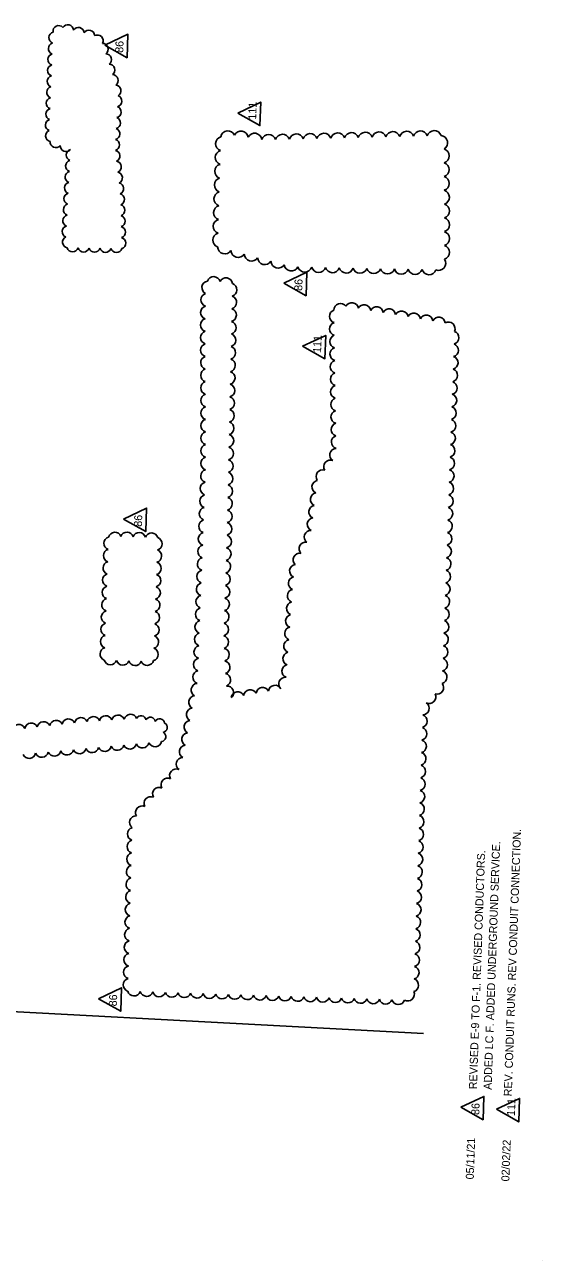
# Model space of a CAD drawing. Extents: x 928669 to 929521, y 636891 to 638153.
# Drawn here: x 929187 to 929497, y 636891 to 637632 of the extents above; entities that cross this region are included whole.
import ezdxf

# ---------------------------------------------------------------- set-up
doc = ezdxf.new("R2010")
doc.units = 0
for name, color, linetype in [('AdhocPoint_dp', 7, 'Continuous'), ('Cloud_dp', 7, 'Continuous'), ('MatchLines_dp', 7, 'Continuous')]:
    doc.layers.add(name, color=color, linetype=linetype)

msp = doc.modelspace()

# ---------------------------------------------------------------- linework, layer by layer
at = {"layer": 'AdhocPoint_dp'}
msp.add_line((929497.23, 636890.88), (929497.23, 636890.88), dxfattribs=at)
at = {"layer": 'Cloud_dp'}
for points in [[(929235.2, 637619.48), (929248.51, 637611.96), (929249, 637626.04)], [(929314.8, 637578.72), (929328.11, 637571.21), (929328.6, 637585.29)], [(929342.46, 637476.74), (929355.77, 637469.23), (929356.26, 637483.31)], [(929353.7, 637438.9), (929367.01, 637431.39), (929367.5, 637445.47)], [(929246.44, 637335.3), (929259.74, 637327.79), (929260.24, 637341.87)], [(929231.39, 637047.73), (929244.7, 637040.22), (929245.19, 637054.29)], [(929448.5, 636982.61), (929461.8, 636975.1), (929462.3, 636989.17)], [(929469.81, 636981.4), (929483.12, 636973.89), (929483.61, 636987.96)]]:
    msp.add_lwpolyline(points, close=True, dxfattribs=at)
for centre, radius, start, end in [((929213.02, 637628.29), 3.44, 2.92703, 147.92703), ((929205.1, 637623.96), 3.44, 105.27092, 250.27092), ((929207.6, 637627.76), 3.44, 43.1629, 188.1629), ((929219.37, 637626.64), 3.44, 2.92703, 147.92703), ((929225.72, 637624.99), 3.44, 2.92703, 147.92703), ((929230.75, 637622.12), 3.44, 332.6769, 117.6769), ((929204.85, 637617.4), 3.44, 105.27092, 250.27092), ((929233.82, 637617.1), 3.44, 305.17358, 90.17358), ((929204.59, 637610.85), 3.44, 105.27092, 250.27092), ((929235.81, 637610.85), 3.44, 305.17358, 90.17358), ((929204.34, 637604.29), 3.44, 105.27092, 250.27092), ((929237.8, 637604.6), 3.44, 305.17358, 90.17358), ((929239.79, 637598.35), 3.44, 305.17358, 90.17358), ((929203.83, 637591.18), 3.44, 105.27092, 250.27092), ((929204.08, 637597.74), 3.44, 105.27092, 250.27092), ((929241.46, 637592.11), 3.44, 299.75137, 84.75137), ((929203.57, 637584.63), 3.44, 105.27092, 250.27092), ((929241.94, 637585.92), 3.44, 284.10958, 69.10958), ((929203.32, 637578.07), 3.44, 105.27092, 250.27092), ((929241.55, 637579.37), 3.44, 284.10958, 69.10958), ((929203.06, 637571.52), 3.44, 105.27092, 250.27092), ((929241.16, 637572.82), 3.44, 284.10958, 69.10958), ((929203.18, 637565.09), 3.44, 111.86507, 256.86507), ((929240.78, 637566.27), 3.44, 284.10958, 69.10958), ((929308.97, 637563.74), 4.33, 24.68742, 169.68742), ((929316.78, 637563.62), 4.33, 8.49645, 153.49645), ((929324.94, 637562.33), 4.33, 8.49645, 153.49645), ((929333.34, 637561.62), 4.34, 16.93077, 161.93077), ((929341.65, 637561.68), 4.33, 18.88115, 163.88115), ((929349.91, 637561.88), 4.33, 18.88115, 163.88115), ((929358.17, 637562.08), 4.33, 18.88115, 163.88115), ((929366.43, 637562.28), 4.33, 18.88115, 163.88115), ((929374.69, 637562.48), 4.33, 18.88115, 163.88115), ((929382.95, 637562.68), 4.33, 18.88115, 163.88115), ((929391.21, 637562.88), 4.33, 18.88115, 163.88115), ((929399.47, 637563.08), 4.33, 18.88115, 163.88115), ((929407.73, 637563.28), 4.33, 18.88115, 163.88115), ((929415.99, 637563.47), 4.33, 18.88115, 163.88115), ((929424.25, 637563.67), 4.33, 18.88115, 163.88115), ((929432.51, 637563.87), 4.33, 18.88115, 163.88115), ((929436.25, 637560.96), 4.33, 300.25152, 85.25152), ((929205.83, 637561.48), 3.44, 175.6731, 320.6731), ((929211.92, 637559.04), 3.44, 175.6731, 320.6731), ((929240.54, 637559.67), 3.44, 286.70334, 71.70334), ((929305.89, 637560.35), 4.33, 105.83297, 250.83297), ((929437.15, 637553.08), 4.33, 287.75579, 72.75579), ((929215.19, 637546.97), 3.44, 104.44225, 249.44225), ((929215.49, 637553.55), 3.44, 105.4204, 250.4204), ((929240.86, 637553), 3.44, 293.9345, 78.9345), ((929241.6, 637546.48), 3.44, 293.9345, 78.9345), ((929305.65, 637552.09), 4.33, 105.83297, 250.83297), ((929214.85, 637540.42), 3.44, 104.44225, 249.44225), ((929242.33, 637539.96), 3.44, 293.9345, 78.9345), ((929305.41, 637543.83), 4.33, 105.83297, 250.83297), ((929437.19, 637544.82), 4.33, 287.75579, 72.75579), ((929214.5, 637533.87), 3.44, 104.44225, 249.44225), ((929243.07, 637533.45), 3.44, 293.9345, 78.9345), ((929305.17, 637535.57), 4.33, 105.83297, 250.83297), ((929437.22, 637536.55), 4.33, 287.75579, 72.75579), ((929214.15, 637527.32), 3.44, 104.44225, 249.44225), ((929243.57, 637526.98), 3.44, 289.97064, 74.97064), ((929304.93, 637527.31), 4.33, 105.83297, 250.83297), ((929437.26, 637528.29), 4.33, 287.75579, 72.75579), ((929213.8, 637520.77), 3.44, 104.44225, 249.44225), ((929243.8, 637520.44), 3.44, 289.01338, 74.01338), ((929304.69, 637519.06), 4.33, 105.83297, 250.83297), ((929437.3, 637520.03), 4.33, 287.75579, 72.75579), ((929213.45, 637514.22), 3.44, 104.44225, 249.44225), ((929243.97, 637513.89), 3.44, 289.01338, 74.01338), ((929304.45, 637510.8), 4.33, 105.83297, 250.83297), ((929437.34, 637511.77), 4.33, 287.75579, 72.75579), ((929213.1, 637507.67), 3.44, 104.44225, 249.44225), ((929244.15, 637507.33), 3.44, 289.01338, 74.01338), ((929304.21, 637502.54), 4.33, 105.83297, 250.83297), ((929437.37, 637503.5), 4.33, 287.75579, 72.75579), ((929213.29, 637501.31), 3.44, 114.12608, 259.12608), ((929215.94, 637498.93), 3.44, 196.77389, 341.77389), ((929244.32, 637500.77), 3.44, 289.01338, 74.01338), ((929307.11, 637498.64), 4.33, 182.52043, 327.52043), ((929437.41, 637495.24), 4.33, 287.75579, 72.75579), ((929222.5, 637498.85), 3.44, 196.77389, 341.77389), ((929229.06, 637498.76), 3.44, 196.77389, 341.77389), ((929235.61, 637498.68), 3.44, 196.77389, 341.77389), ((929242.17, 637498.6), 3.44, 196.77389, 341.77389), ((929315.09, 637496.5), 4.33, 182.52043, 327.52043), ((929323.08, 637494.36), 4.33, 182.52043, 327.52043), ((929331.06, 637492.23), 4.33, 182.52043, 327.52043), ((929435.09, 637488.76), 4.33, 247.90789, 32.90789), ((929339.04, 637490.09), 4.33, 182.52043, 327.52043), ((929346.98, 637488.41), 4.33, 188.59745, 333.59745), ((929355.01, 637487.7), 4.33, 196.29364, 341.29364), ((929363.27, 637487.53), 4.33, 196.29364, 341.29364), ((929371.54, 637487.36), 4.33, 196.29364, 341.29364), ((929379.8, 637487.18), 4.33, 196.29364, 341.29364), ((929388.06, 637487.01), 4.33, 196.29364, 341.29364), ((929396.32, 637486.83), 4.33, 196.29364, 341.29364), ((929404.58, 637486.66), 4.33, 196.29364, 341.29364), ((929412.84, 637486.49), 4.33, 196.29364, 341.29364), ((929421.1, 637486.31), 4.33, 196.29364, 341.29364), ((929429.36, 637486.14), 4.33, 196.29364, 341.29364), ((929297.31, 637474.09), 3.95, 99.12031, 244.12031), ((929300.43, 637476.72), 3.95, 16.27485, 161.27485), ((929307.72, 637475.98), 3.95, 7.11778, 152.11778), ((929310.37, 637472.73), 3.95, 286.27485, 71.27485), ((929296.69, 637466.74), 3.95, 106.27485, 251.27485), ((929310.21, 637465.19), 3.95, 286.27485, 71.27485), ((929296.56, 637459.2), 3.95, 106.77607, 251.77607), ((929310.05, 637457.65), 3.95, 286.27485, 71.27485), ((929376.38, 637460.63), 3.95, 35.3298, 180.3298), ((929383.13, 637461.12), 3.95, 8.00095, 153.00095), ((929390.57, 637459.88), 3.95, 8.00095, 153.00095), ((929398.01, 637458.63), 3.95, 8.00095, 153.00095), ((929405.45, 637457.39), 3.95, 8.00095, 153.00095), ((929296.52, 637451.68), 3.95, 107.61007, 252.61007), ((929309.89, 637450.1), 3.95, 286.27485, 71.27485), ((929373.68, 637456.86), 3.95, 108.39751, 253.39751), ((929412.89, 637456.14), 3.95, 8.00095, 153.00095), ((929420.33, 637454.9), 3.95, 8.00095, 153.00095), ((929427.77, 637453.65), 3.95, 8.00095, 153.00095), ((929435.21, 637452.41), 3.95, 8.00095, 153.00095), ((929441.08, 637449.52), 3.95, 334.60056, 119.60056), ((929296.54, 637444.13), 3.95, 107.61007, 252.61007), ((929309.73, 637442.56), 3.95, 286.27485, 71.27485), ((929373.8, 637449.31), 3.95, 108.39751, 253.39751), ((929443.34, 637444.1), 3.95, 285.49782, 70.49782), ((929296.55, 637436.59), 3.95, 107.61007, 252.61007), ((929309.57, 637435.02), 3.95, 286.27485, 71.27485), ((929373.92, 637441.77), 3.95, 108.39751, 253.39751), ((929443.07, 637436.56), 3.95, 285.49782, 70.49782), ((929296.57, 637429.05), 3.95, 107.61007, 252.61007), ((929309.41, 637427.48), 3.95, 286.27485, 71.27485), ((929374.03, 637434.23), 3.95, 108.39751, 253.39751), ((929442.81, 637429.02), 3.95, 285.49782, 70.49782), ((929296.58, 637421.5), 3.95, 107.61007, 252.61007), ((929374.15, 637426.69), 3.95, 108.39751, 253.39751), ((929442.54, 637421.48), 3.95, 285.49782, 70.49782), ((929296.59, 637413.96), 3.95, 107.61007, 252.61007), ((929309.24, 637419.94), 3.95, 286.27485, 71.27485), ((929374.27, 637419.14), 3.95, 108.39751, 253.39751), ((929442.28, 637413.94), 3.95, 285.49782, 70.49782), ((929296.61, 637406.42), 3.95, 107.61007, 252.61007), ((929309.08, 637412.4), 3.95, 286.27485, 71.27485), ((929374.39, 637411.6), 3.95, 108.39751, 253.39751), ((929442.02, 637406.4), 3.95, 285.49782, 70.49782), ((929296.62, 637398.87), 3.95, 107.61007, 252.61007), ((929308.92, 637404.85), 3.95, 286.27485, 71.27485), ((929374.51, 637404.06), 3.95, 108.39751, 253.39751), ((929441.75, 637398.86), 3.95, 285.49782, 70.49782), ((929296.64, 637391.33), 3.95, 107.61007, 252.61007), ((929308.76, 637397.31), 3.95, 286.27485, 71.27485), ((929374.62, 637396.52), 3.95, 108.39751, 253.39751), ((929441.49, 637391.32), 3.95, 285.49782, 70.49782), ((929296.65, 637383.79), 3.95, 107.61007, 252.61007), ((929308.6, 637389.77), 3.95, 286.27485, 71.27485), ((929374.74, 637388.97), 3.95, 108.39751, 253.39751), ((929441.23, 637383.79), 3.95, 285.49782, 70.49782), ((929296.67, 637376.24), 3.95, 107.61007, 252.61007), ((929308.44, 637382.23), 3.95, 286.27485, 71.27485), ((929374.86, 637381.43), 3.96, 108.39751, 253.39751), ((929440.96, 637376.25), 3.95, 285.49782, 70.49782), ((929296.68, 637368.7), 3.95, 107.61007, 252.61007), ((929308.28, 637374.69), 3.95, 286.27485, 71.27485), ((929373.89, 637373.69), 3.95, 92.3374, 237.3374), ((929440.7, 637368.71), 3.95, 285.49782, 70.49782), ((929296.57, 637361.12), 3.95, 105.69752, 250.69752), ((929308.11, 637367.15), 3.95, 286.27485, 71.27485), ((929365.68, 637360.81), 3.95, 71.34179, 216.34179), ((929370.27, 637366.7), 3.95, 67.83576, 212.83576), ((929440.44, 637361.17), 3.95, 285.49782, 70.49782), ((929296.31, 637353.57), 3.95, 105.31641, 250.31641), ((929307.95, 637359.6), 3.95, 286.27485, 71.27485), ((929363.21, 637354.57), 3.95, 100.45276, 245.45276), ((929440.17, 637353.63), 3.95, 285.49782, 70.49782), ((929296.02, 637346.04), 3.95, 105.31641, 250.31641), ((929307.79, 637352.06), 3.95, 286.27485, 71.27485), ((929362.29, 637347.09), 3.95, 100.45276, 245.45276), ((929439.91, 637346.09), 3.95, 285.49782, 70.49782), ((929295.73, 637338.5), 3.95, 105.31641, 250.31641), ((929307.63, 637344.52), 3.95, 286.27485, 71.27485), ((929361.36, 637339.6), 3.95, 100.45276, 245.45276), ((929439.65, 637338.55), 3.95, 285.49782, 70.49782), ((929307.47, 637336.98), 3.95, 286.27485, 71.27485), ((929360.43, 637332.11), 3.96, 100.45276, 245.45276), ((929248.47, 637323.64), 3.87, 15.49782, 160.49782), ((929295.44, 637330.96), 3.95, 105.31641, 250.31641), ((929307.31, 637329.44), 3.95, 286.27485, 71.27485), ((929358.61, 637324.57), 3.95, 87.3831, 232.3831), ((929439.38, 637331.01), 3.95, 285.49782, 70.49782), ((929238.51, 637320.76), 3.87, 105.49782, 250.49782), ((929241.22, 637323.55), 3.86, 21.00152, 166.00152), ((929255.84, 637323.39), 3.87, 15.49782, 160.49782), ((929263.21, 637323.13), 3.87, 15.49782, 160.49782), ((929265.64, 637320.52), 3.87, 285.49782, 70.49782), ((929295.16, 637323.42), 3.95, 105.31641, 250.31641), ((929307.11, 637321.91), 3.95, 285.67169, 70.67169), ((929355.49, 637317.54), 3.95, 79.64936, 224.64936), ((929439.12, 637323.48), 3.95, 285.49782, 70.49782), ((929238.25, 637313.39), 3.87, 105.49782, 250.49782), ((929265.39, 637313.15), 3.87, 285.49782, 70.49782), ((929294.87, 637315.88), 3.95, 105.31641, 250.31641), ((929306.86, 637314.37), 3.95, 285.59211, 70.59211), ((929351.96, 637310.88), 3.95, 79.64936, 224.64936), ((929438.85, 637315.94), 3.95, 285.49782, 70.49782), ((929237.99, 637306.02), 3.87, 105.49782, 250.49782), ((929265.13, 637305.78), 3.87, 285.49782, 70.49782), ((929294.58, 637308.35), 3.95, 105.31641, 250.31641), ((929306.61, 637306.83), 3.95, 285.59211, 70.59211), ((929349.84, 637304.2), 3.96, 100.03505, 245.03505), ((929438.59, 637308.4), 3.95, 285.49782, 70.49782), ((929237.74, 637298.65), 3.87, 105.49782, 250.49782), ((929264.87, 637298.41), 3.87, 285.49782, 70.49782), ((929294.29, 637300.81), 3.95, 105.31641, 250.31641), ((929306.36, 637299.29), 3.95, 285.59211, 70.59211), ((929349.08, 637296.77), 3.95, 103.32391, 248.32391), ((929438.33, 637300.86), 3.95, 285.49782, 70.49782), ((929237.48, 637291.29), 3.87, 105.49782, 250.49782), ((929264.61, 637291.04), 3.87, 285.49782, 70.49782), ((929294.01, 637293.27), 3.95, 105.31641, 250.31641), ((929306.11, 637291.75), 3.95, 285.59211, 70.59211), ((929348.53, 637289.24), 3.95, 103.32391, 248.32391), ((929438.06, 637293.32), 3.95, 285.49782, 70.49782), ((929237.22, 637283.92), 3.87, 105.49782, 250.49782), ((929264.36, 637283.68), 3.87, 285.49782, 70.49782), ((929293.72, 637285.73), 3.95, 105.31641, 250.31641), ((929305.86, 637284.21), 3.95, 285.59211, 70.59211), ((929347.98, 637281.72), 3.95, 103.32391, 248.32391), ((929437.8, 637285.78), 3.95, 285.49782, 70.49782), ((929236.96, 637276.55), 3.87, 105.49782, 250.49782), ((929264.1, 637276.31), 3.87, 285.49782, 70.49782), ((929293.43, 637278.19), 3.95, 105.31641, 250.31641), ((929305.61, 637276.68), 3.95, 285.59211, 70.59211), ((929347.43, 637274.2), 3.95, 103.32391, 248.32391), ((929437.54, 637278.24), 3.95, 285.49782, 70.49782), ((929236.71, 637269.18), 3.87, 105.49782, 250.49782), ((929263.84, 637268.94), 3.87, 285.49782, 70.49782), ((929293.15, 637270.66), 3.95, 105.31641, 250.31641), ((929305.36, 637269.14), 3.95, 285.59211, 70.59211), ((929346.89, 637266.67), 3.95, 103.32391, 248.32391), ((929437.27, 637270.7), 3.95, 285.49782, 70.49782), ((929236.45, 637261.81), 3.87, 105.49782, 250.49782), ((929263.58, 637261.57), 3.87, 285.49782, 70.49782), ((929292.86, 637263.12), 3.95, 105.31641, 250.31641), ((929305.39, 637261.51), 3.95, 289.9101, 74.9101), ((929346.34, 637259.15), 3.95, 103.32391, 248.32391), ((929437.01, 637263.17), 3.95, 285.49782, 70.49782), ((929236.19, 637254.44), 3.87, 105.49782, 250.49782), ((929263.33, 637254.2), 3.87, 285.49782, 70.49782), ((929292.57, 637255.58), 3.95, 105.31641, 250.31641), ((929305.76, 637253.96), 3.95, 290.73051, 75.73051), ((929345.79, 637251.63), 3.95, 103.32391, 248.32391), ((929436.75, 637255.63), 3.95, 285.49782, 70.49782), ((929238.62, 637251.83), 3.87, 195.49782, 340.49782), ((929245.99, 637251.58), 3.87, 195.49782, 340.49782), ((929253.36, 637251.32), 3.87, 195.49782, 340.49782), ((929260.61, 637251.41), 3.86, 201.00152, 346.00152), ((929292.28, 637248.04), 3.95, 105.31641, 250.31641), ((929306.19, 637246.43), 3.95, 290.73051, 75.73051), ((929345.24, 637244.1), 3.96, 103.32391, 248.32391), ((929436.48, 637248.09), 3.95, 285.49782, 70.49782), ((929291.88, 637240.48), 3.95, 103.59365, 248.59365), ((929306.61, 637238.89), 3.95, 290.73051, 75.73051), ((929343.32, 637236.5), 3.95, 83.29548, 228.29548), ((929436.22, 637240.55), 3.95, 285.49782, 70.49782), ((929290.89, 637232.87), 3.95, 96.63256, 241.63256), ((929308.4, 637231.26), 3.96, 310.65902, 95.65902), ((929314.9, 637227.75), 3.96, 27.60024, 172.60024), ((929322.33, 637229.07), 3.95, 27.60024, 172.60024), ((929329.75, 637230.39), 3.95, 27.60024, 172.60024), ((929337.18, 637231.72), 3.95, 27.60024, 172.60024), ((929434.18, 637234.28), 3.95, 253.37458, 38.37458), ((929289.47, 637225.46), 3.95, 96.63256, 241.63256), ((929425.56, 637221.83), 3.95, 271.42998, 56.42998), ((929429.55, 637228.64), 3.95, 242.86964, 27.86964), ((929228.38, 637213.02), 3.89, 21.02193, 166.02193), ((929235.78, 637213.48), 3.89, 21.02193, 166.02193), ((929243.19, 637213.94), 3.89, 21.02193, 166.02193), ((929250.6, 637214.39), 3.89, 21.02193, 166.02193), ((929256.89, 637214.44), 2.98, 8.08604, 153.08604), ((929262.49, 637213.51), 2.98, 8.08604, 153.08604), ((929288.05, 637218.05), 3.95, 96.63256, 241.63256), ((929424.35, 637214.15), 3.95, 285.63881, 70.63881), ((929183.63, 637208.23), 3.94, 23.82829, 168.82829), ((929191.11, 637209.06), 3.94, 23.82829, 168.82829), ((929198.58, 637209.89), 3.94, 23.82829, 168.82829), ((929206.05, 637210.71), 3.94, 23.82829, 168.82829), ((929213.52, 637211.54), 3.94, 23.82829, 168.82829), ((929221, 637212.37), 3.94, 23.82829, 168.82829), ((929268.1, 637212.58), 2.98, 8.08604, 153.08604), ((929269.71, 637210.36), 2.95, 278.08604, 63.08604), ((929286.63, 637210.64), 3.95, 96.63256, 241.63256), ((929424.1, 637206.61), 3.95, 285.63881, 70.63881), ((929265.33, 637202.72), 3.97, 202.7882, 347.7882), ((929268.79, 637204.81), 2.95, 278.08604, 63.08604), ((929285.21, 637203.23), 3.95, 96.63256, 241.63256), ((929423.86, 637199.07), 3.95, 285.63881, 70.63881), ((929189.9, 637195.74), 3.97, 202.7882, 347.7882), ((929197.45, 637196.44), 3.97, 202.7882, 347.7882), ((929204.99, 637197.14), 3.97, 202.7882, 347.7882), ((929212.53, 637197.83), 3.97, 202.7882, 347.7882), ((929220.07, 637198.53), 3.97, 202.7882, 347.7882), ((929227.61, 637199.23), 3.97, 202.7882, 347.7882), ((929235.16, 637199.93), 3.97, 202.7882, 347.7882), ((929242.7, 637200.63), 3.97, 202.7882, 347.7882), ((929250.24, 637201.32), 3.97, 202.7882, 347.7882), ((929257.78, 637202.02), 3.97, 202.7882, 347.7882), ((929283.78, 637195.82), 3.95, 96.63256, 241.63256), ((929423.61, 637191.53), 3.95, 285.63881, 70.63881), ((929281.91, 637188.39), 3.95, 90.0306, 235.0306), ((929423.37, 637183.99), 3.95, 285.63881, 70.63881), ((929272.85, 637176.02), 3.95, 64.86082, 209.86082), ((929277.96, 637181.57), 3.95, 64.86082, 209.86082), ((929423.12, 637176.45), 3.95, 285.63881, 70.63881), ((929267.74, 637170.47), 3.95, 64.86082, 209.86082), ((929422.88, 637168.91), 3.95, 285.63881, 70.63881), ((929262.63, 637164.92), 3.95, 64.86082, 209.86082), ((929422.63, 637161.37), 3.95, 285.63881, 70.63881), ((929253.98, 637153.45), 3.95, 88.3908, 233.3908), ((929257.52, 637159.37), 3.95, 64.86082, 209.86082), ((929422.39, 637153.83), 3.95, 285.63881, 70.63881), ((929252.71, 637146.47), 3.95, 105.90323, 250.90323), ((929422.14, 637146.29), 3.95, 285.63881, 70.63881), ((929252.49, 637138.93), 3.95, 105.90323, 250.90323), ((929421.9, 637138.75), 3.95, 285.63881, 70.63881), ((929252.28, 637131.39), 3.95, 105.90323, 250.90323), ((929421.65, 637131.21), 3.95, 285.63881, 70.63881), ((929252.07, 637123.85), 3.95, 105.90323, 250.90323), ((929251.86, 637116.31), 3.95, 105.90323, 250.90323), ((929421.41, 637123.67), 3.95, 285.63881, 70.63881), ((929421.16, 637116.13), 3.95, 285.63881, 70.63881), ((929251.65, 637108.77), 3.95, 105.90323, 250.90323), ((929420.92, 637108.59), 3.95, 285.63881, 70.63881), ((929251.44, 637101.23), 3.95, 105.90323, 250.90323), ((929420.67, 637101.06), 3.95, 285.63881, 70.63881), ((929251.23, 637093.69), 3.95, 105.90323, 250.90323), ((929420.43, 637093.52), 3.95, 285.63881, 70.63881), ((929251.02, 637086.15), 3.95, 105.90323, 250.90323), ((929420.18, 637085.98), 3.95, 285.63881, 70.63881), ((929250.81, 637078.61), 3.95, 105.90323, 250.90323), ((929419.94, 637078.44), 3.95, 285.63881, 70.63881), ((929250.6, 637071.07), 3.95, 105.90323, 250.90323), ((929419.69, 637070.9), 3.95, 285.63881, 70.63881), ((929250.39, 637063.53), 3.95, 105.90323, 250.90323), ((929419.45, 637063.36), 3.95, 285.63881, 70.63881), ((929250.18, 637055.99), 3.95, 105.90323, 250.90323), ((929419.2, 637055.82), 3.95, 285.63881, 70.63881), ((929252.7, 637053.32), 3.95, 195.63881, 340.63881), ((929260.24, 637053.07), 3.95, 195.63881, 340.63881), ((929267.78, 637052.83), 3.95, 195.63881, 340.63881), ((929275.32, 637052.58), 3.95, 195.63881, 340.63881), ((929282.85, 637052.34), 3.95, 195.63881, 340.63881), ((929290.39, 637052.09), 3.95, 195.63881, 340.63881), ((929297.93, 637051.85), 3.95, 195.63881, 340.63881), ((929305.47, 637051.6), 3.95, 195.63881, 340.63881), ((929313.01, 637051.36), 3.95, 195.63881, 340.63881), ((929320.55, 637051.11), 3.95, 195.63881, 340.63881), ((929328.09, 637050.87), 3.95, 195.63881, 340.63881), ((929335.63, 637050.62), 3.95, 195.63881, 340.63881), ((929343.17, 637050.38), 3.95, 195.63881, 340.63881), ((929350.71, 637050.13), 3.95, 195.63881, 340.63881), ((929358.25, 637049.89), 3.95, 195.63881, 340.63881), ((929365.79, 637049.64), 3.95, 195.63881, 340.63881), ((929373.33, 637049.4), 3.95, 195.63881, 340.63881), ((929380.87, 637049.15), 3.95, 195.63881, 340.63881), ((929388.41, 637048.91), 3.95, 195.63881, 340.63881), ((929395.95, 637048.66), 3.95, 195.63881, 340.63881), ((929403.48, 637048.42), 3.95, 195.63881, 340.63881), ((929411.02, 637048.17), 3.95, 195.63881, 340.63881), ((929416.7, 637050.3), 3.95, 240.55669, 25.55669)]:
    msp.add_arc(centre, radius, start, end, dxfattribs=at)
at = {"layer": 'MatchLines_dp'}
msp.add_lwpolyline([(929426.17, 637026.85), (929066.68, 637046.02), (928774.81, 637061.58)], dxfattribs=at)

# ---------------------------------------------------------------- texts
at = {"layer": 'Cloud_dp'}
for s, p in [('86', (929246.2, 637614.83)), ('111', (929325.82, 637574.7)), ('86', (929353.45, 637472.09)), ('111', (929364.72, 637434.88)), ('86', (929257.43, 637330.65)), ('REV. CONDUIT RUNS. REV CONDUIT CONNECTION.', (929478.96, 636989.12)), ('REVISED E-9 TO F-1. REVISED CONDUCTORS. ', (929458.06, 636993.37)), ('ADDED LC F. ADDED UNDERGROUND SERVICE.', (929466.85, 636993.06)), ('86', (929242.38, 637043.08)), ('111', (929480.83, 636977.38)), ('86', (929459.49, 636977.96)), ('05/11/21', (929456.17, 636939.33)), ('02/02/22', (929477.49, 636938.12))]:
    msp.add_text(s, height=4.8, rotation=87.99782, dxfattribs=at).set_placement(p)

doc.saveas('drawing.dxf')
